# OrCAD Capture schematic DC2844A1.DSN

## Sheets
1 PAGE3: size B; title: DSP6713 SYSTEM; rev: V1.0; company: WITH DIGITAL POWER MANAGEMENT; note: DUAL 30A OUTPUT STEP-DOWN uMODULE REGULATOR
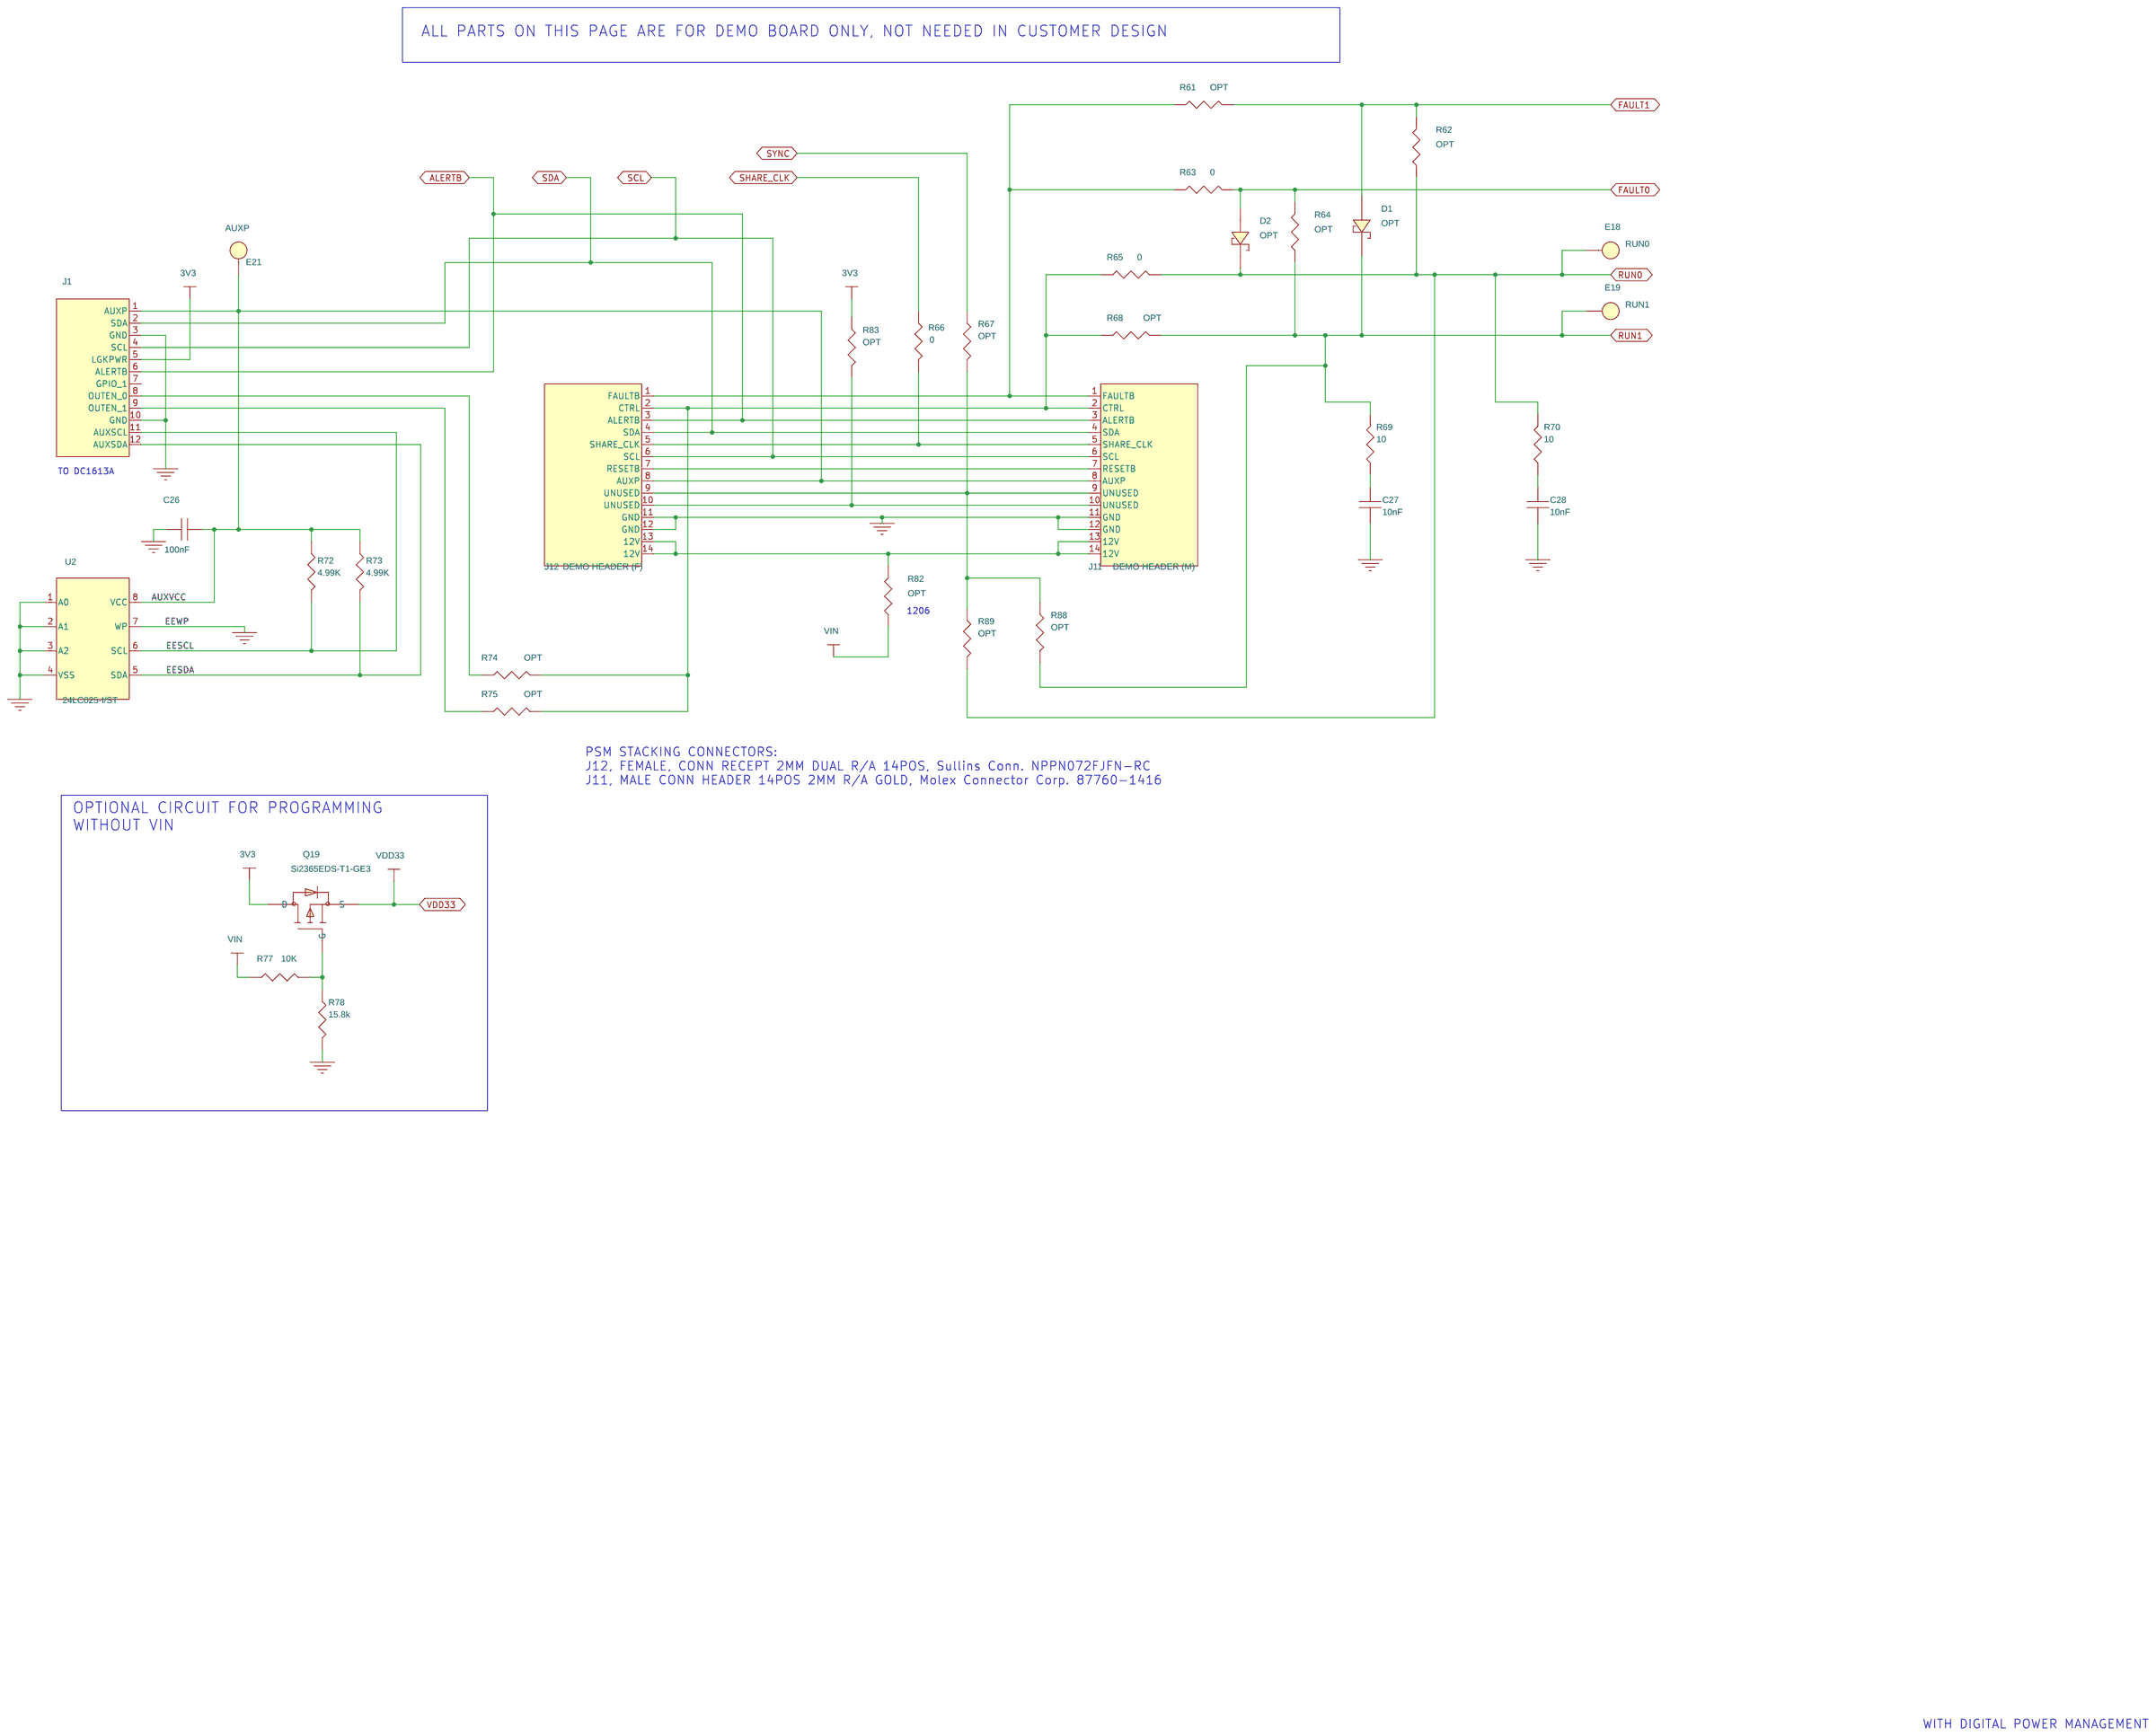
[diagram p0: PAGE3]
2 PAGE1: size C
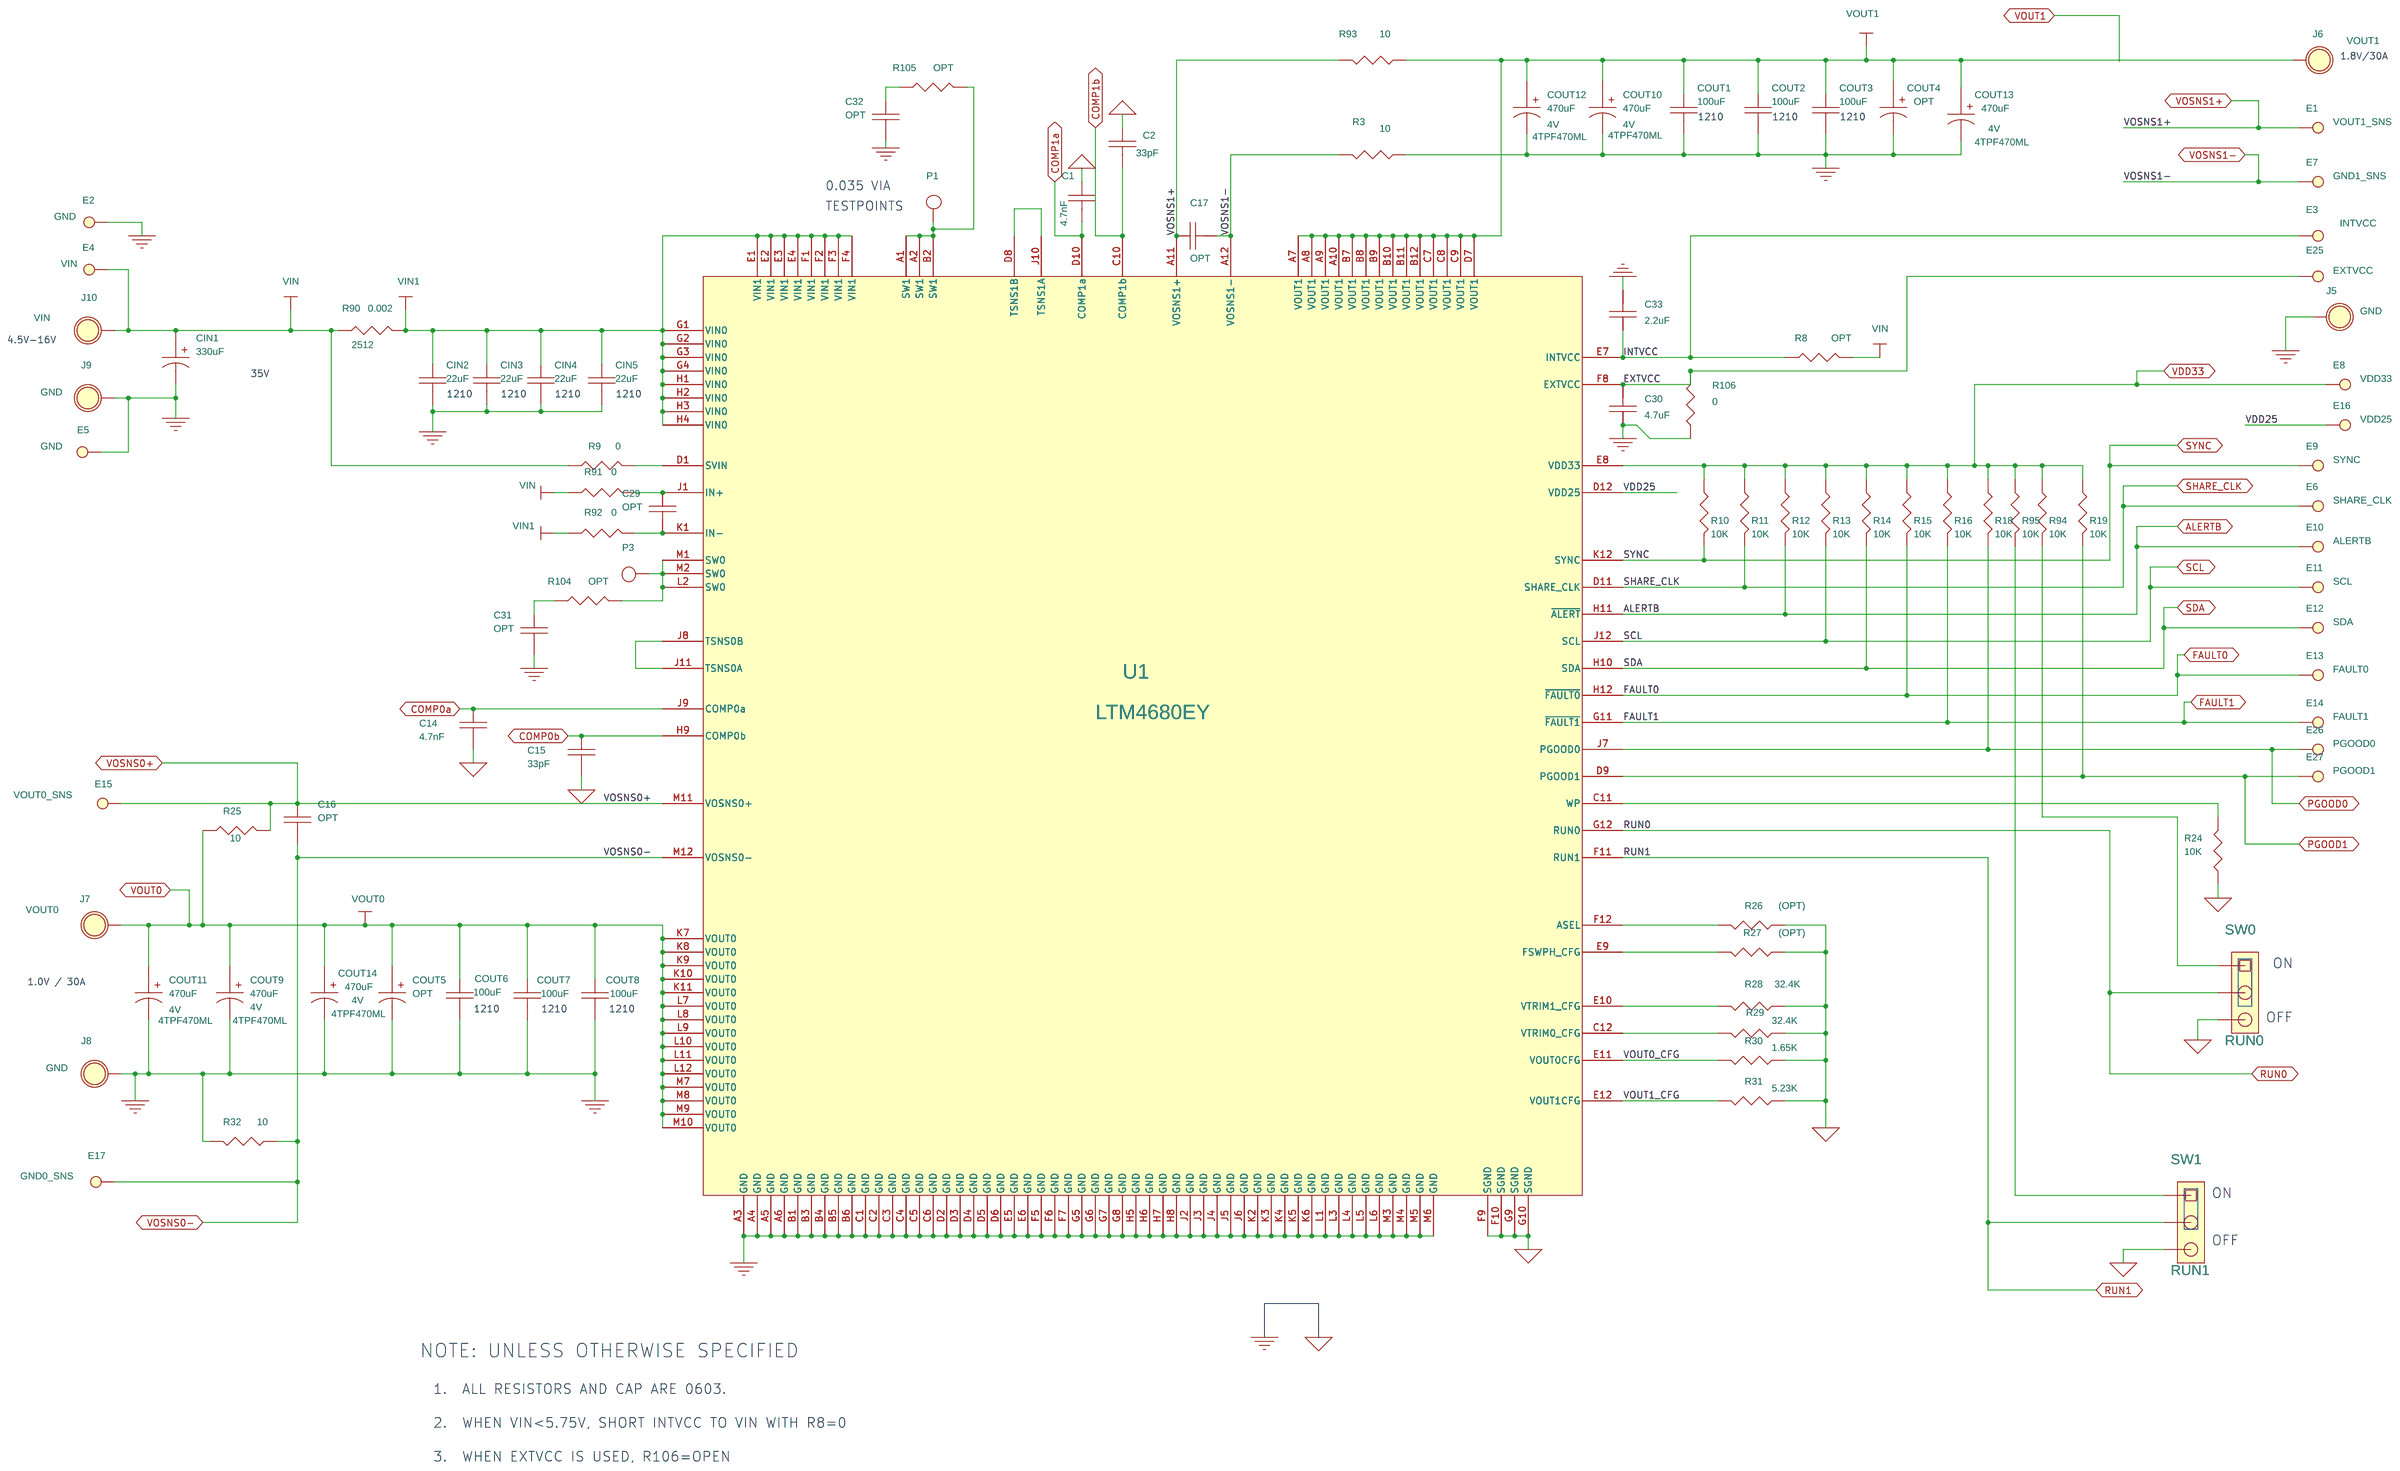
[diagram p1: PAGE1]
3 PAGE2: size Custom
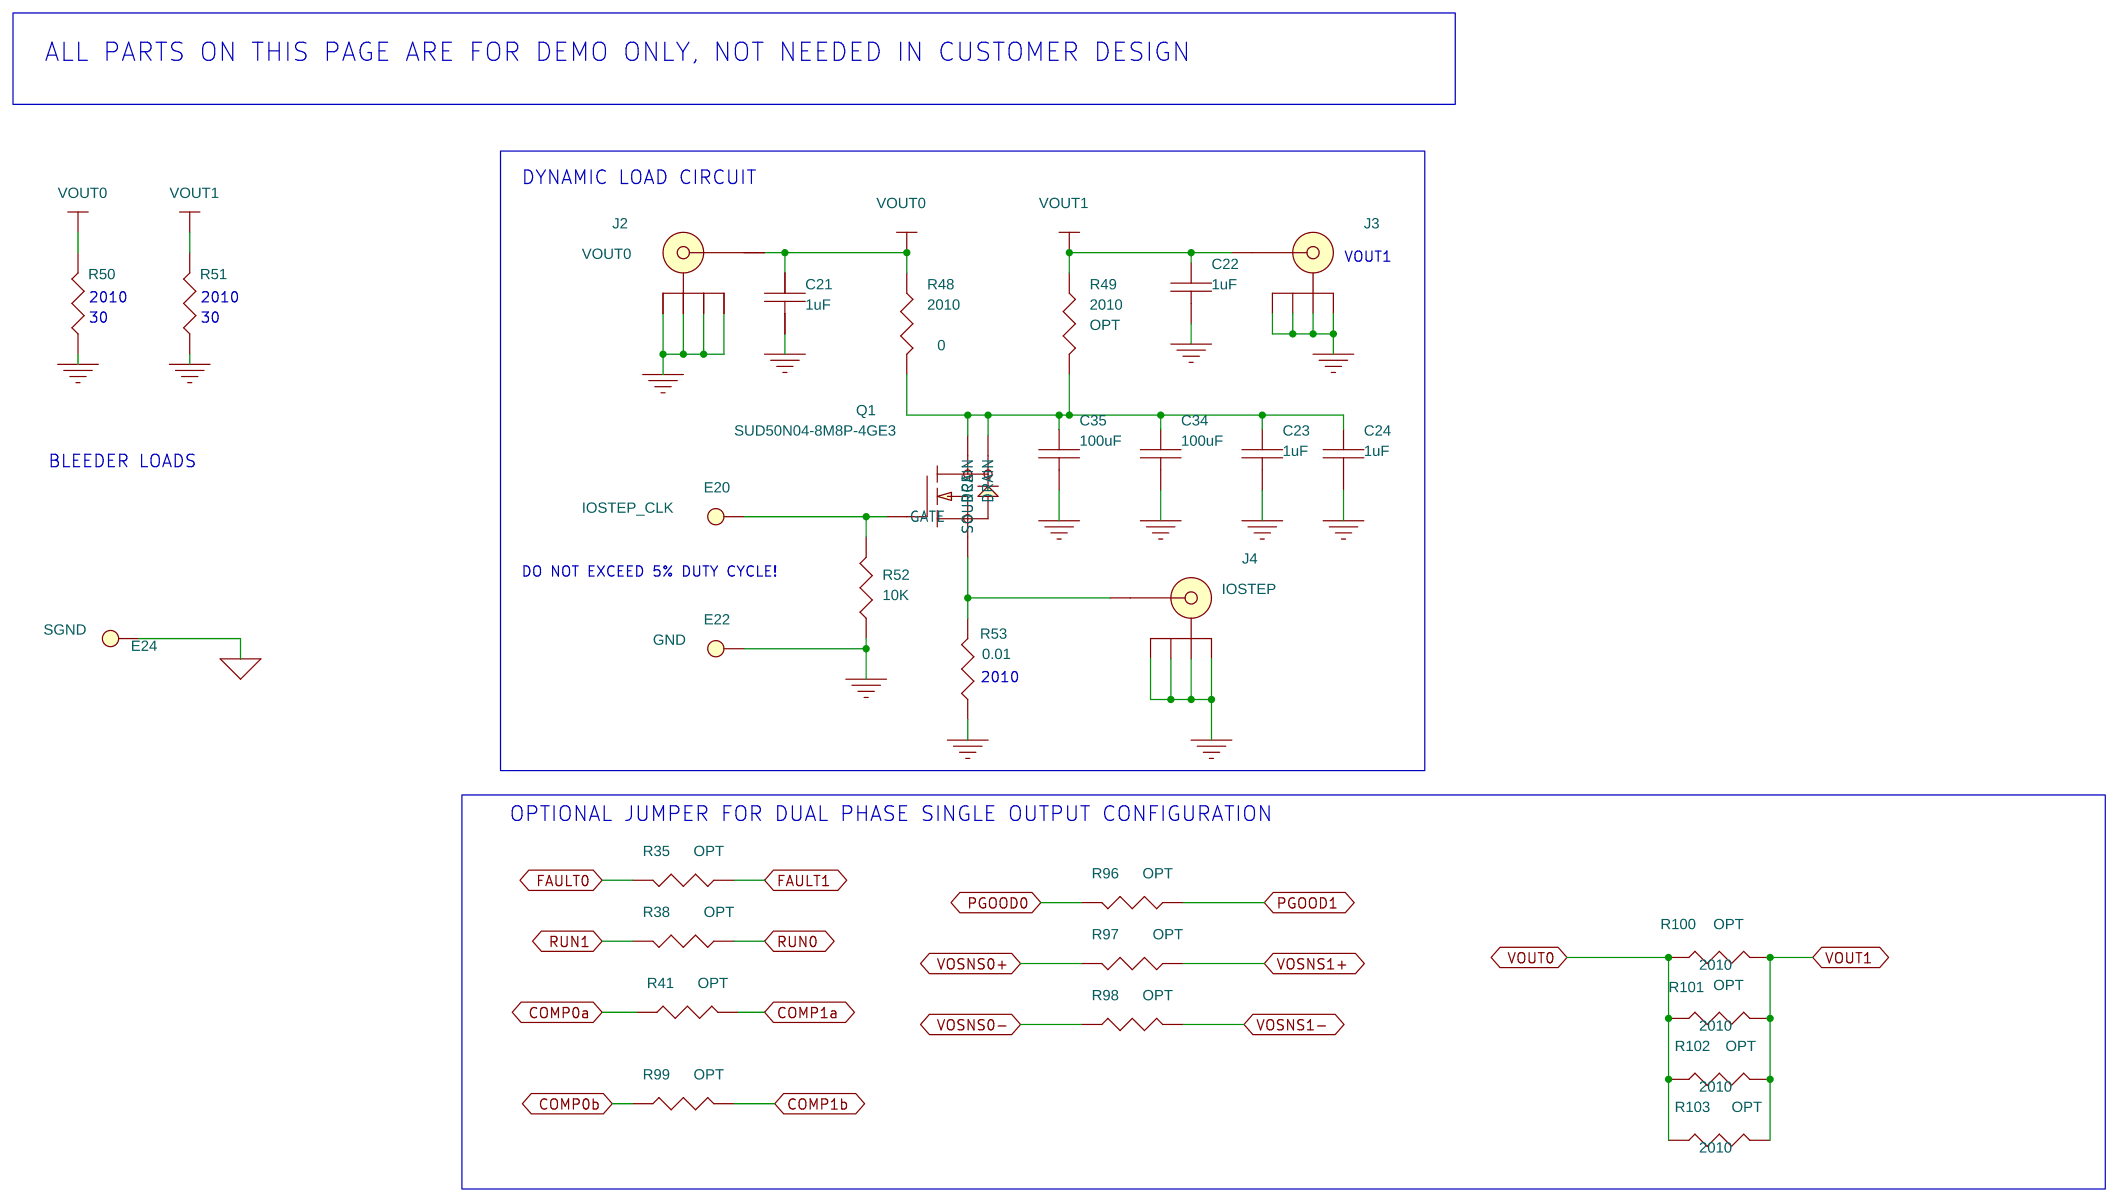
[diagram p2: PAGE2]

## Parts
sheet PAGE1
C1  4.7nF  [0603]
C2  33pF  [0603]
C14  4.7nF  [0603]
C15  33pF  [0603]
C16  OPT  [0603]
C17  OPT  [0603]
C29  OPT  [0603]
C30  4.7uF  [0603]
C31  OPT  [0603]
C32  OPT  [0603]
C33  2.2uF  [0603]
CIN1  330uF  [SANYO-F8]
CIN2  22uF  [1210]
CIN3  22uF  [1210]
CIN4  22uF  [1210]
CIN5  22uF  [1210]
COUT1  100uF  [1210]
COUT2  100uF  [1210]
COUT3  100uF  [1210]
COUT4  OPT  [D3L]
COUT5  OPT  [D3L]
COUT6  100uF  [1210]
COUT7  100uF  [1210]
COUT8  100uF  [1210]
COUT9  470uF  [D3L]
COUT10  470uF  [D3L]
COUT11  470uF  [D3L]
COUT12  470uF  [D3L]
COUT13  470uF  [D3L]
COUT14  470uF  [D3L]
E1  TURRETS  [TURRETS]
E2  GND  [TURRETS]
E3  INTVCC  [TURRETS]
E4  TURRETS  [TURRETS]
E5  GND  [TURRETS]
E6  TURRETS  [TURRETS]
E7  TURRETS  [TURRETS]
E8  VDD33  [TURRETS]
E9  TURRETS  [TURRETS]
E10  TURRETS  [TURRETS]
E11  TURRETS  [TURRETS]
E12  TURRETS  [TURRETS]
E13  TURRETS  [TURRETS]
E14  TURRETS  [TURRETS]
E15  TURRETS  [TURRETS]
E16  VDD25  [TURRETS]
E17  TURRETS  [TURRETS]
E25  EXTVCC  [TURRETS]
E26  TURRETS  [TURRETS]
E27  TURRETS  [TURRETS]
J5  BANANA SMALL  [CON\LUG\10]
J6  BANANA SMALL  [CON\LUG\10]
J7  BANANA SMALL  [CON\LUG\10]
J8  BANANA SMALL  [CON\LUG\10]
J9  BANANA SMALL  [CON\LUG\10]
J10  BANANA SMALL  [CON\LUG\10]
P1  TURRETS  [PAD]
P3  TURRETS  [PAD]
R3  10  [0603]
R8  OPT  [0603]
R9  0  [0603]
R10  10K  [0603]
R11  10K  [0603]
R12  10K  [0603]
R13  10K  [0603]
R14  10K  [0603]
R15  10K  [0603]
R16  10K  [0603]
R18  10K  [0603]
R19  10K  [0603]
R24  10K  [0603]
R25  10  [0603]
R26  (OPT)  [0603]
R27  (OPT)  [0603]
R28  32.4K  [0603]
R29  32.4K  [0603]
R30  5.23K  [0603]
R31  1.65K  [0603]
R32  10  [0603]
R90  0.002  [2512]
R91  0  [0603]
R92  0  [0603]
R93  10  [0603]
R94  10K  [0603]
R95  10K  [0603]
R104  OPT  [0805]
R105  OPT  [0805]
R106  0  [0603]
SW0  3 Pins 2mm Ctrs.  [HD1X3-079]
SW1  3 Pins 2mm Ctrs.  [HD1X3-079]
U1  LTM4680EY  [a]
sheet PAGE2
C21  1uF  [0603]
C22  1uF  [0603]
C23  1uF  [0805]
C24  1uF  [0603]
C34  100uF  [1210]
C35  100uF  [1210]
E20  IOSTEP_CLK  [TURRETS]
E22  GND  [TURRETS]
E24  SGND  [TURRETS]
J2  VOUT0  [BNC]
J3  XXX  [BNC]
J4  IOSTEP  [BNC]
Q1  SUD50N04-8M8P-4GE3  [TO252]
R35  OPT  [0603]
R38  OPT  [0603]
R41  OPT  [0603]
R48  2010  [2010]
R49  2010  [2010]
R50  30  [2512SENSE]
R51  30  [2512SENSE]
R52  10K  [0603]
R53  0.01  [2010]
R96  OPT  [0603]
R97  OPT  [0603]
R98  OPT  [0603]
R99  OPT  [0603]
R100  OPT  [2010]
R101  OPT  [2010]
R102  OPT  [2010]
R103  OPT  [2010]
sheet PAGE3
C26  100nF  [0603]
C27  10nF  [0603]
C28  10nF  [0603]
D1  OPT  [SOD323]
D2  OPT  [SOD323]
E18  RUN0  [TURRETS]
E19  RUN1  [TURRETS]
E21  AUXP  [TURRETS]
J1  HD2X6-079  [HD2X6-079-MOLEX]
J11  DEMO HEADER (M)  [NPPN072FJFN]
J12  DEMO HEADER (F)  [NPPN072FJFN-RC]
Q19  Si2365EDS-T1-GE3  [SOT-23]
R61  OPT  [0603]
R62  OPT  [0603]
R63  0  [0603]
R64  OPT  [0603]
R65  0  [0603]
R66  0  [0603]
R67  OPT  [0603]
R68  OPT  [0603]
R69  10  [0603]
R70  10  [0603]
R72  4.99K  [0603]
R73  4.99K  [0603]
R74  OPT  [0603]
R75  OPT  [0603]
R77  10K  [0603]
R78  15.8k  [0603]
R82  OPT  [1206]
R83  OPT  [0603]
R88  OPT  [0603]
R89  OPT  [0603]
U2  24LC025-I/ST  [TSSOP-8_4.4MM]

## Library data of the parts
C1 C2 C14-C17 C29-C33 = CAP0603_1: Component: cap; Manufacturer: TDK; Manufacturer P/N: C1608C0G1H102J; Tolerance: 5%; Type: cer 0603; Vendor: Digikey; Vendor P/N: 445-1293-1-ND; Volts/Amps/Watts: 50V
CIN1 = CAPR12X5_0: Component: cap; Manufacturer: SANYO; Tolerance: 20%; Type: OS-CON; Volts/Amps/Watts: 16V
CIN2-CIN5 = CAP1210_1: Component: cap; Manufacturer: Taiyo Yuden; Manufacturer P/N: GMK325BJ106KN-T; Tolerance: 10%; Type: cer 1210; Vendor: Digikey; Vendor P/N: 587-1439-1-ND; Volts/Amps/Watts: 35V
C34 C35 COUT1 = CAP0603_1: Component: cap; Manufacturer: TDK; Manufacturer P/N: C3225X5R0J107M; Tolerance: 20%; Type: cer 1210 X5R; Vendor: Digikey; Vendor P/N: 445-1437-1-ND; Volts/Amps/Watts: 6.3v
COUT2 COUT3 COUT6-COUT8 = CAP0603_1: Component: cap; Manufacturer: TDK; Manufacturer P/N: C3225X5R0J107M; Part Type: CAP1210; Tolerance: 20%; Type: cer 1210 X5R; Vendor: Digikey; Vendor P/N: 445-1437-1-ND; Volts/Amps/Watts: 6.3v
COUT4 COUT5 = CAPR12X5_0: Component: cap; Manufacturer: SANYO; Manufacturer P/N: EEFGX0E471R; Tolerance: 20%; Type: SP-CAP; Volts/Amps/Watts: 2.5V
COUT9-COUT14 = CAPR12X5_0: Component: cap; Manufacturer: SANYO; Manufacturer P/N: 4TPF470ML; Tolerance: 20%; Type: SP-CAP; Volts/Amps/Watts: 4V
E1 = TURRETS_1: Component: tp; Label: VOUT1_SNS; Vendor: Digikey; Vendor P/N: 1593-2K-ND
E2 E5 E22 = TURRETS_1: Component: tp; Manufacturer: Keystone; Manufacturer P/N: 1593-2; Vendor: Digikey; Vendor P/N: 1593-2K-ND
E3 E8 E16 E20 E24 E25 = TURRETS_1: Component: tp; Label: GND; Manufacturer: Keystone; Manufacturer P/N: 1593-2; Vendor: Digikey; Vendor P/N: 1593-2K-ND
E4 = TURRETS_1: Component: tp; Label: VIN; Manufacturer: Keystone; Manufacturer P/N: 1593-2; Vendor: Digikey; Vendor P/N: 1593-2K-ND
E6 = TURRETS_1: Component: tp; Label: SHARE_CLK; Manufacturer: Keystone; Manufacturer P/N: 1593-2; Vendor: Digikey; Vendor P/N: 1593-2K-ND
E7 = TURRETS_1: Component: tp; Label: GND1_SNS; Vendor: Digikey; Vendor P/N: 1593-2K-ND
E9 = TURRETS_1: Component: tp; Label: SYNC; Manufacturer: Keystone; Manufacturer P/N: 1593-2; Vendor: Digikey; Vendor P/N: 1593-2K-ND
E10 = TURRETS_1: Component: tp; Label: ALERTB; Manufacturer: Keystone; Manufacturer P/N: 1593-2; Vendor: Digikey; Vendor P/N: 1593-2K-ND
E11 = TURRETS_1: Component: tp; Label: SCL; Manufacturer: Keystone; Manufacturer P/N: 1593-2; Vendor: Digikey; Vendor P/N: 1593-2K-ND
E12 = TURRETS_1: Component: tp; Label: SDA; Manufacturer: Keystone; Manufacturer P/N: 1593-2; Vendor: Digikey; Vendor P/N: 1593-2K-ND
E13 = TURRETS_1: Component: tp; Label: FAULT0; Manufacturer: Keystone; Manufacturer P/N: 1593-2; Vendor: Digikey; Vendor P/N: 1593-2K-ND
E14 = TURRETS_1: Component: tp; Label: FAULT1; Manufacturer: Keystone; Manufacturer P/N: 1593-2; Vendor: Digikey; Vendor P/N: 1593-2K-ND
E15 = TURRETS_1: Component: tp; Label: VOUT0_SNS; Vendor: Digikey; Vendor P/N: 1593-2K-ND
E17 = TURRETS_1: Component: tp; Label: GND0_SNS; Vendor: Digikey; Vendor P/N: 1593-2K-ND
E26 = TURRETS_1: Component: tp; Label: PGOOD0; Manufacturer: Keystone; Manufacturer P/N: 1593-2; Vendor: Digikey; Vendor P/N: 1593-2K-ND
E27 = TURRETS_1: Component: tp; Label: PGOOD1; Manufacturer: Keystone; Manufacturer P/N: 1593-2; Vendor: Digikey; Vendor P/N: 1593-2K-ND
J5 J8 J9 = BANANA_SMALL_0: Component: conn; Label: GND
J6 = BANANA_SMALL_0: Component: conn; Label: VOUT1
J7 = BANANA_SMALL_0: Component: conn; Label: VOUT0
J10 = BANANA_SMALL_0: Component: conn; Label: VIN
P1 P3 = PAD_2: Component: tp; Label: <Label>; Vendor: Digikey; Vendor P/N: 1593-2K-ND
R3 = RES0603_9: Label: 0; Manufacturer: Rohm; Manufacturer P/N: RHM0.0GCT-ND; Tolerance: 5%; Vendor: Digikey; Vendor P/N: RHM0.0GCT-ND; Volts/Amps/Watts: 0.1W
R8 = RES0603_9: Label: OPT 0; Manufacturer: Rohm; Manufacturer P/N: RHM0.0GCT-ND; Vendor: Digikey
R9 R41 R98 R99 = RES0603_3
R10-R16 R18 R19 R24 R29 R30 R91 R92 R94 R95 R104-R106 = RES0603_9: Manufacturer: ROHM; Manufacturer P/N: MCR03EZPFX1002; Vendor: Digikey; Vendor P/N: RHM10.0KHCT-ND; Volts/Amps/Watts: 0.1W
R25 = RES0603_9: Manufacturer: Rohm; Manufacturer P/N: MCR03EZPFX1000; Vendor: Digikey; Vendor P/N: RHM100HCT-ND; Volts/Amps/Watts: 0.1W
R26 R27 = RES0603_9: Manufacturer: Panasonic; Manufacturer P/N: ERJ-3EKF2002V; Vendor: Digikey; Vendor P/N: P20.0KHCT-ND; Volts/Amps/Watts: 0.1W
R28 = RES0603_9: Manufacturer: Panasonic; Manufacturer P/N: ERJ-3EKF1000V; Vendor: Digikey; Vendor P/N: P100HCT-ND; Volts/Amps/Watts: 0.1W
R31 = RES0603_9: Manufacturer: Panasonic; Manufacturer P/N: ERJ-3EKF1021V; Vendor: Digikey; Vendor P/N: P1.02KHCT-ND; Volts/Amps/Watts: 0.1W
R32 = RES0603_9: Manufacturer: Yageo; Manufacturer P/N: RC0603JR-070RL; Tolerance: 5%; Vendor: Digikey; Vendor P/N: 311-0.0GRCT-ND; Volts/Amps/Watts: 0.1W
R90 R100-R103 = RES2512_0: Tolerance: <Tolerance>
R93 = RES0603_9: Manufacturer: Rohm; Manufacturer P/N: RHM0.0GCT-ND; Tolerance: 5%; Vendor: Digikey; Vendor P/N: RHM0.0GCT-ND; Volts/Amps/Watts: 0.1W
SW0 = Commcon2802s03g2_7: 11th Part Field: OFF; 12th Part Field: RUN0; 9th Part Field: ON
SW1 = Commcon2802s03g2_7: 11th Part Field: OFF; 12th Part Field: RUN1; 9th Part Field: ON
U1 = LTC3880-M0001_45: Component: IC; Manufacturer: LTC; Manufacturer P/N: LTC3880_M0001; Vendor: LTC; Vendor P/N: LTC3880_M0001
C21 C22 C24 = CAP0603_1
C23 = CAP1206_1: Manufacturer: Kemet; Manufacturer P/N: C1206C106K8RACTU; Tolerance: 10%; Type: cer 1206 X7R; Vendor: Digikey; Vendor P/N: 399-4937-1-ND; Volts/Amps/Watts: 10V
J2 J4 = BNC5-SCH_0
J3 = BNC5-SCH_0: CONN,BNC,5 PINS; Part Number: CONNEX 112404
Q1 = IRF540_0
R35 R38 R96 R97 = RES0603_9: Label: OPT 0; Manufacturer: Rohm; Manufacturer P/N: RHM0.0GCT-ND; Tolerance: 5%; Vendor: Digikey; Vendor P/N: RHM0.0GCT-ND; Volts/Amps/Watts: 0.1W
R48 = RES2512_0: Tolerance: 0
R49 = RES2512_0: Tolerance: OPT
R50 = RES0603_5: Label: 1W; Manufacturer: VISHAY; Manufacturer P/N: CRCW251230R0JNEG; Tolerance: 5%; Vendor: Digikey; Vendor P/N: 541-30XCT-ND; Volts/Amps/Watts: 0.1W
R51 = RES0603_6: Label: 1W; Tolerance: 5%; Vendor: Digikey; Vendor P/N: 541-30XCT-ND; Volts/Amps/Watts: 0.1W
R52 = RES0603_9
R53 = RES0603_5: Label: 1W; Manufacturer: VISHAY; Manufacturer P/N: CRCW251230R0JNEG; Part Type: 2512; Tolerance: 5%; Vendor: Digikey; Vendor P/N: 541-30XCT-ND; Volts/Amps/Watts: 0.1W
C26 = CAP_NP: CAP, 0603 100nF 20% 16V X7R; Part Number: AVX 0603YC104MAT2A
C27 C28 = CAP_NP: CAP, 0603 10nF 10% 25V X7R; Part Number: AVX 06033C103KAT2A
D1 D2 = DIODE_SCHOTTKY_9: DIODE, SCHOTTKY 30V, 100mA; Part Number: CENTRAL SEMI CMDSH-3-TR
E18 E19 E21 = E_0: TURRET; Part Number: MILL MAX 2501-2-00-80-00-00-07-0
J1 = HD2X6-079-PMBUS_2: HEADER, 12PIN 2mm STR DL; Label: DC1427A HEADER; Manufacturer: MOLEX; Manufacturer P/N: 87831-1220; Part Number: FCI 98414-G06-12ULF; Type: header 12POS 2MM VERT; Vendor: Digikey; Vendor P/N: WM18561-ND
J11 = PMBUS_CONNECTOR20_3: CONN, SOCKET 20PIN  DUAL ROW R/A; Component: con; Manufacturer: Mill Max; Manufacturer P/N: 803-93-020-20-001; Part Number: MILL MAX 803-93-020-20-001; Type: conn  RA 20 dual row; Vendor: LTC; Vendor P/N: 803-93-020-20-001
J12 = PMBUS_HEADER20_3: HEADER, 20PIN DUAL ROW R/A; Component: con; Manufacturer: Mill Max; Manufacturer P/N: 802-40-020-20-0001; Part Number: MILL MAX 802-40-020-20-0001; Type: header RA 20 dual row; Vendor: LTC; Vendor P/N: 802-40-020-20-001
Q19 = P-MOSFET: XSTR, N-CHANNEL DMOS FET; Part Number: VISHAY TP0101K-T1-E3
R61 R63 R65 R68 = RES0603_0: RES, 0603 0 OHMS JUMPER; Label: OPT 0; Manufacturer: Rohm; Manufacturer P/N: RHM0.0GCT-ND; Part Number: VISHAY CRCW06030000Z0EA; Tolerance: 5%; Vendor: Digikey; Vendor P/N: RHM0.0GCT-ND; Volts/Amps/Watts: 0.1W
R62 R64 R67 R75 R83 R88 R89 = RES0603_0: RES, 0603 OPTION; Label: OPT 0; Manufacturer: Rohm; Manufacturer P/N: RHM0.0GCT-ND; Part Number: OPTION; Tolerance: 5%; Vendor: Digikey; Vendor P/N: RHM0.0GCT-ND; Volts/Amps/Watts: 0.1W
R66 = RES0603_0: RES, 0603 0 OHMS JUMPER; Manufacturer: Rohm; Manufacturer P/N: RHM0.0GCT-ND; Part Number: VISHAY CRCW06030000Z0EA; Tolerance: 5%; Vendor: Digikey; Vendor P/N: RHM0.0GCT-ND; Volts/Amps/Watts: 0.1W
R69 R70 = RES0603_1: RES, 0603 10 OHMS 5% 1/10W; Manufacturer: Rohm; Manufacturer P/N: RHM0.0GCT-ND; Part Number: VISHAY CRCW060310R0JNEA; Tolerance: 5%; Vendor: Digikey; Vendor P/N: RHM0.0GCT-ND; Volts/Amps/Watts: 0.1W
R72 R73 = RES0603_0: RES, 0603 4.99K OHMS 1% 1/10W; Manufacturer: ROHM; Manufacturer P/N: MCR03EZPFX4991; Part Number: VISHAY CRCW06034K99FKEA; Vendor: Digikey; Vendor P/N: RHM4.99KHCT-ND; Volts/Amps/Watts: 0.1w
R74 R82 = RES0603_3: RES, 0603 OPTION; Label: OPT 0; Manufacturer: Rohm; Manufacturer P/N: RHM0.0GCT-ND; Part Number: OPTION; Tolerance: 5%; Vendor: Digikey; Vendor P/N: RHM0.0GCT-ND; Volts/Amps/Watts: 0.1W
R77 = RES0603_11: RES, 0603 10K OHMS 5% 1/10W; Part Number: VISHAY CRCW060310K0JNEA
R78 = RES0603_11: RES, 0603 15.8K OHMS 1% 1/10W; Part Number: VISHAY CRCW060315K8FKEA
U2 = 24LC025-I_SN: IC, 24LC05-I/ST; Part Number: MICROCHIP 24LC025-I/ST

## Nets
3V3: J1.5(LGKPWR) Q19.3(D) R83.1
GND_POWER: C21.2 C22.2 C23.2 C24.2 C26.2 C27.2 C28.2 C30.1 C31.2 C32.2 C33.2 C34.2 C35.2 CIN1.2 CIN2.2 CIN3.2 CIN4.2 CIN5.2 COUT1.2 COUT2.2 COUT3.2 COUT4.2 COUT5.2 COUT6.2 COUT7.2 COUT8.2 COUT9.2 COUT10.2 COUT11.2 COUT12.2 COUT13.2 COUT14.2 E2.1(TP) E5.1(TP) E22.1(TP) J1.3(GND) J1.10(GND) J2.2 J2.3 J2.4 J2.5 J3.2 J3.3 J3.4 J3.5 J4.2 J4.3 J4.4 J4.5 J5.1(TP) J8.1(TP) J9.1(TP) J11.11(GND) J11.12(GND) J12.11(GND) J12.12(GND) R3.2 R32.2 R50.1 R51.1 R52.2 R53.1 R78.2 R106.1 U1.A3(GND) U1.A4(GND) U1.A5(GND) U1.A6(GND) U1.B1(GND) U1.B3(GND) U1.B4(GND) U1.B5(GND) U1.B6(GND) U1.C1(GND) U1.C2(GND) U1.C3(GND) U1.C4(GND) U1.C5(GND) U1.C6(GND) U1.D2(GND) U1.D3(GND) U1.D4(GND) U1.D5(GND) U1.D6(GND) U1.E5(GND) U1.E6(GND) U1.F5(GND) U1.F6(GND) U1.F7(GND) U1.G5(GND) U1.G6(GND) U1.G7(GND) U1.G8(GND) U1.H5(GND) U1.H6(GND) U1.H7(GND) U1.H8(GND) U1.J2(GND) U1.J3(GND) U1.J4(GND) U1.J5(GND) U1.J6(GND) U1.K2(GND) U1.K3(GND) U1.K4(GND) U1.K5(GND) U1.K6(GND) U1.L1(GND) U1.L3(GND) U1.L4(GND) U1.L5(GND) U1.L6(GND) U1.M3(GND) U1.M4(GND) U1.M5(GND) U1.M6(GND) U2.1(A0) U2.2(A1) U2.3(A2) U2.4(VSS) U2.7(WP)
GND_SIGNAL: C1.1 C2.1 C14.2 C15.2 E24.1(TP) R24.1 R26.1 R27.1 R28.1 R29.1 R30.1 R31.1 SW0.3 SW1.3 U1.F9(SGND) U1.F10(SGND) U1.G9(SGND) U1.G10(SGND)
VDD25: E16.1(TP) U1.D12(VDD25)
VDD33: E8.1(TP) Q19.2(S) R10.1 R11.1 R12.1 R13.1 R14.1 R15.1 R16.1 R18.1 R19.1 R94.1 R95.1 U1.E8(VDD33)
VIN: CIN1.1 E4.1(TP) J10.1(TP) R8.1 R9.1 R77.1 R82.1 R90.1 R91.1
VIN1: CIN2.1 CIN3.1 CIN4.1 CIN5.1 R90.2 R92.1 U1.E1(VIN1) U1.E2(VIN1) U1.E3(VIN1) U1.E4(VIN1) U1.F1(VIN1) U1.F2(VIN1) U1.F3(VIN1) U1.F4(VIN1) U1.G1(VIN0) U1.G2(VIN0) U1.G3(VIN0) U1.G4(VIN0) U1.H1(VIN0) U1.H2(VIN0) U1.H3(VIN0) U1.H4(VIN0)
ALERTB: E10.1(TP) J1.6(ALERTB) J11.3(ALERTB) J12.3(ALERTB) R12.2 U1.H11(~{ALERT})
AUXVCC: C26.1 E21.1(A) J1.1(AUXP) J11.8(AUXP) J12.8(AUXP) R72.1 R73.1 U2.8(VCC)
COMP0a: C14.1 R41.1 U1.J9(COMP0a)
COMP0b: C15.1 R99.1 U1.H9(COMP0b)
COMP1a: C1.2 R41.2 U1.D10(COMP1a)
COMP1b: C2.2 R99.2 U1.C10(COMP1b)
EESCL: J1.11(AUXSCL) R72.2 U2.6(SCL)
EESDA: J1.12(AUXSDA) R73.2 U2.5(SDA)
EXTVCC: C30.2 E25.1(TP) R106.2 U1.F8(EXTVCC)
FAULT0: D2.2(ANODE) E13.1(TP) R15.2 R35.2 R63.2 R64.2 U1.H12(~{FAULT0})
FAULT1: D1.2(ANODE) E14.1(TP) R16.2 R35.1 R61.2 R62.2 U1.G11(~{FAULT1})
INTVCC: C33.1 E3.1(TP) R8.2 U1.E7(INTVCC)
PGOOD0: E26.1(TP) R18.2 R96.2 U1.J7(PGOOD0)
PGOOD1: E27.1(TP) R19.2 R96.1 U1.D9(PGOOD1)
RUN0: D2.1(CATHODE) E18.1(A) R38.2 R62.1 R65.2 R70.2 R89.2 SW0.2 U1.G12(RUN0)
RUN1: D1.1(CATHODE) E19.1(A) R38.1 R64.1 R68.2 R69.2 R88.2 SW1.2 U1.F11(RUN1)
SCL: E11.1(TP) J1.4(SCL) J11.6(SCL) J12.6(SCL) R13.2 U1.J12(SCL)
SDA: E12.1(TP) J1.2(SDA) J11.4(SDA) J12.4(SDA) R14.2 U1.H10(SDA)
SHARE_CLK: E6.1(TP) R11.2 R66.1 U1.D11(SHARE_CLK)
SYNC: E9.1(TP) R10.2 R67.1 U1.K12(SYNC)
VOSNS0+: C16.1 E15.1(TP) R25.1 R97.1 U1.M11(VOSNS0+)
VOSNS0-: C16.2 E17.1(TP) R32.1 R98.1 U1.M12(VOSNS0-)
VOSNS1+: C17.1 E1.1(TP) R93.2 R97.2 U1.A11(VOSNS1+)
VOSNS1-: C17.2 E7.1(TP) R3.1 R98.2 U1.A12(VOSNS1-)
VOUT0: C21.1 COUT5.1 COUT6.1 COUT7.1 COUT8.1 COUT9.1 COUT11.1 COUT14.1 J2.1 J7.1(TP) R25.2 R48.1 R50.2 R100.1 R101.1 R102.1 R103.1 U1.K7(VOUT0) U1.K8(VOUT0) U1.K9(VOUT0) U1.K10(VOUT0) U1.K11(VOUT0) U1.L7(VOUT0) U1.L8(VOUT0) U1.L9(VOUT0) U1.L10(VOUT0) U1.L11(VOUT0) U1.L12(VOUT0) U1.M7(VOUT0) U1.M8(VOUT0) U1.M9(VOUT0) U1.M10(VOUT0)
VOUT0_CFG: R30.2 U1.E11(VOUT0CFG)
VOUT1: C22.1 COUT1.1 COUT2.1 COUT3.1 COUT4.1 COUT10.1 COUT12.1 COUT13.1 J3.1 J6.1(TP) R49.1 R51.2 R93.1 R100.2 R101.2 R102.2 R103.2 U1.A7(VOUT1) U1.A8(VOUT1) U1.A9(VOUT1) U1.A10(VOUT1) U1.B7(VOUT1) U1.B8(VOUT1) U1.B9(VOUT1) U1.B10(VOUT1) U1.B11(VOUT1) U1.B12(VOUT1) U1.C7(VOUT1) U1.C8(VOUT1) U1.C9(VOUT1) U1.D7(VOUT1)
VOUT1_CFG: R31.2 U1.E12(VOUT1CFG)
N16779036: E20.1(TP) Q1.1(GATE) R52.1
N16779111: J4.1 Q1.3(SOURCE) R53.2
N16779469: C23.1 C24.1 C34.1 C35.1 Q1.2(DRAIN) Q1.4(DRAIN) R48.2 R49.2
N16992964: R9.2 U1.D1(SVIN)
N17166430: P1.1(TP) R105.2 U1.A1(SW1) U1.A2(SW1) U1.B2(SW1)
N17222714: R26.2 U1.F12(ASEL)
N17223298: R27.2 U1.E9(FSWPH_CFG)
N17223884: R28.2 U1.E10(VTRIM1_CFG)
N17224472: R29.2 U1.C12(VTRIM0_CFG)
N18333697: J11.1(FAULTB) J12.1(FAULTB) R61.1 R63.1
N18333715: J1.8(OUTEN_0) R74.1
N18333717: J1.9(OUTEN_1) R75.1
N18333729: J11.2(CTRL) J12.2(CTRL) R65.1 R68.1 R74.2 R75.2
N18333791: C27.1 R69.1
N18333793: C28.1 R70.1
N18333815: Q19.1(G) R77.2 R78.1
N18333849: J11.5(SHARE_CLK) J12.5(SHARE_CLK) R66.2
N18333851: J11.7(RESETB) J12.7(RESETB)
N18333853: J11.9(UNUSED) J12.9(UNUSED) R67.2 R88.1 R89.1
N18333865: J11.13(12V) J11.14(12V) J12.13(12V) J12.14(12V) R82.2
N18333941: J11.10(UNUSED) J12.10(UNUSED) R83.2
N18377351: U1.D8(TSNS1B) U1.J10(TSNS1A)
N18377392: U1.J8(TSNS0B) U1.J11(TSNS0A)
N18421268: R95.2 SW1.1
N18437001: P3.1(TP) R104.2 U1.L2(SW0) U1.M1(SW0) U1.M2(SW0)
N18440006: C29.1 R91.2 U1.J1(IN+)
N18440037: C29.2 R92.2 U1.K1(IN-)
N18449385: R24.2 U1.C11(WP)
N18450678: R94.2 SW0.1
N18468612: C31.1 R104.1
N18469531: C32.1 R105.1

Not connected (* = marked no-connect by the designer): J1 7(GPIO_1)

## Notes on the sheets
sheet 1
- ALL PARTS ON THIS PAGE ARE FOR DEMO BOARD ONLY, NOT NEEDED IN CUSTOMER DESIGN
- TO DC1613A
- 1206
- PSM STACKING CONNECTORS:
  J12, FEMALE, CONN RECEPT 2MM DUAL R/A 14POS, Sullins Conn. NPPN072FJFN-RC
  J11, MALE CONN HEADER 14POS 2MM R/A GOLD, Molex Connector Corp. 87760-1416
- OPTIONAL CIRCUIT FOR PROGRAMMING
  WITHOUT VIN
- WITH DIGITAL POWER MANAGEMENT
sheet 2
- 1.8V/30A
- 1210
- 1210
- 1210
- 0.035 VIA
- TESTPOINTS
- 4.5V-16V
- 35V
- 1210
- 1210
- 1210
- 1210
- ON
- 1.0V / 30A
- 1210
- 1210
- 1210
- OFF
- ON
- OFF
- NOTE: UNLESS OTHERWISE SPECIFIED
- 1.  ALL RESISTORS AND CAP ARE 0603.
- 2.  WHEN VIN<5.75V, SHORT INTVCC TO VIN WITH R8=0
- 3.  WHEN EXTVCC IS USED, R106=OPEN
sheet 3
- ALL PARTS ON THIS PAGE ARE FOR DEMO ONLY, NOT NEEDED IN CUSTOMER DESIGN
- DYNAMIC LOAD CIRCUIT
- VOUT1
- 2010
- 2010
- 30
- 30
- BLEEDER LOADS
- DO NOT EXCEED 5% DUTY CYCLE!
- 2010
- OPTIONAL JUMPER FOR DUAL PHASE SINGLE OUTPUT CONFIGURATION
